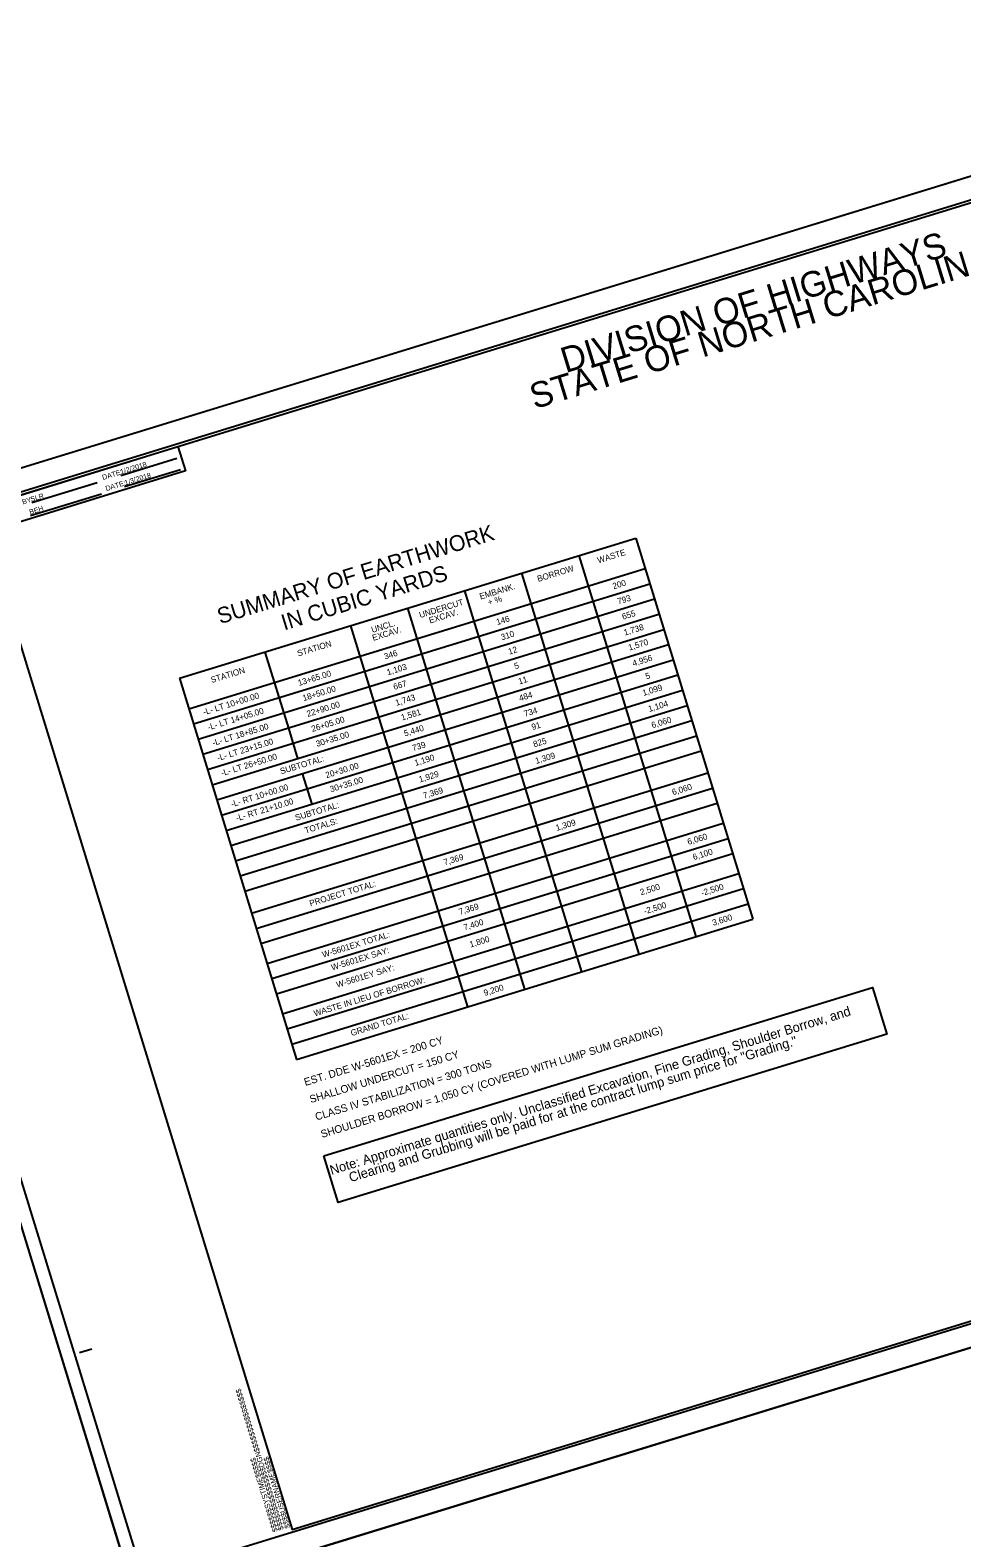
# Model space of a CAD drawing. Extents: x 2528815 to 2532488, y 739965 to 742287.
# Drawn here: x 2530077 to 2530992, y 740714 to 742195 of the extents above; entities that cross this region are included whole.
import ezdxf

# ---------------------------------------------------------------- set-up
doc = ezdxf.new("R2010")
doc.units = 0
for name, color, linetype in [('Prop Grid Mask', 7, 'Continuous'), ('Prop XSC Text', 7, 'Continuous'), ('Sheet Cutting Line CELL', 7, 'Continuous'), ('Sheet Data Field CELL', 7, 'Continuous'), ('Sheet Plot Border Inside CELL', 7, 'Continuous'), ('Sheet Plot Border Outside CELL', 7, 'Continuous'), ('Sheet Summary Combination CELL', 7, 'Continuous'), ('Sheet Summary Combination Grid CELL', 7, 'Continuous'), ('Sheet Summary Earthwork CELL', 7, 'Continuous')]:
    doc.layers.add(name, color=color, linetype=linetype)

msp = doc.modelspace()

# ---------------------------------------------------------------- linework, layer by layer
at = {"layer": 'Prop Grid Mask'}
msp.add_lwpolyline([(2530365.3, 741089.1), (2530904.3, 741254.7), (2530918.4, 741208.8), (2530379.4, 741043.2)], close=True, dxfattribs=at)
at = {"layer": 'Sheet Cutting Line CELL'}
for p, q in [((2531468.4, 742195.3), (2529858.7, 741700.6)), ((2529858.7, 741700.6), (2530181.8, 740649.1)), ((2531791.5, 741143.8), (2530181.8, 740649.1))]:
    msp.add_line(p, q, dxfattribs=at)
at = {"layer": 'Sheet Plot Border Inside CELL'}
msp.add_lwpolyline([(2531470.7, 742172.5), (2529877.7, 741682.9), (2530187.7, 740674.4), (2531780.6, 741163.9)], close=True, dxfattribs=at)
at = {"layer": 'Sheet Plot Border Outside CELL'}
msp.add_lwpolyline([(2531468.4, 742195.3), (2529858.7, 741700.6), (2530181.8, 740649.1), (2531791.5, 741143.8)], close=True, dxfattribs=at)
at = {"layer": 'Sheet Summary Combination CELL'}
for p, q in [((2530165.9, 741757.8), (2530220.9, 741774.7)), ((2530169.4, 741746.8), (2530224.4, 741763.7)), ((2530077.1, 741718.4), (2530146.8, 741739.8)), ((2530078.6, 741731.1), (2530142.7, 741750.8)), ((2530336.2, 741593), (2530336.2, 741593)), ((2530343.7, 741595.1), (2530343.7, 741595.1)), ((2530354.4, 741598.7), (2530354.4, 741598.7)), ((2530361.2, 741600.6), (2530361.2, 741600.6)), ((2530125.3, 740895.9), (2530137.3, 740899.6)), ((2530283.9, 740885.6), (2530283.9, 740885.6))]:
    msp.add_line(p, q, dxfattribs=at)
for points in [[(2531459.5, 742166.4), (2530025.7, 741725.7), (2530334.1, 740722), (2531767.9, 741162.7)], [(2530025.7, 741725.7), (2530221.9, 741786), (2530229.3, 741762.1), (2530033, 741701.8)]]:
    msp.add_lwpolyline(points, close=True, dxfattribs=at)
at = {"layer": 'Sheet Summary Combination Grid CELL'}
for p, q in [((2530223.4, 741558.4), (2530671.7, 741696.1)), ((2530671.7, 741696.1), (2530786.7, 741321.8)), ((2530615.7, 741678.9), (2530730.7, 741304.6)), ((2530615.7, 741678.9), (2530615.7, 741678.9)), ((2530232.6, 741528.5), (2530680.9, 741666.3)), ((2530237.2, 741513.6), (2530685.5, 741651.3)), ((2530559.6, 741661.7), (2530674.7, 741287.3)), ((2530241.8, 741498.6), (2530690.1, 741636.4)), ((2530503.6, 741644.5), (2530618.6, 741270.1)), ((2530246.4, 741483.7), (2530694.6, 741621.4)), ((2530447.5, 741627.2), (2530562.6, 741252.9)), ((2530251, 741468.8), (2530699.2, 741606.5)), ((2530391.5, 741610), (2530506.5, 741235.7)), ((2530255.6, 741453.8), (2530703.8, 741591.6)), ((2530255.6, 741453.8), (2530703.8, 741591.6)), ((2530260.2, 741438.9), (2530708.4, 741576.6)), ((2530307.5, 741584.2), (2530330.5, 741509.5)), ((2530264.8, 741424), (2530713, 741561.7)), ((2530223.4, 741558.4), (2530338.5, 741184)), ((2530269.3, 741409), (2530717.6, 741546.8)), ((2530269.3, 741409), (2530717.6, 741546.8)), ((2530273.9, 741394.1), (2530722.2, 741531.8)), ((2530278.5, 741379.1), (2530726.8, 741516.9)), ((2530283.1, 741364.2), (2530731.4, 741502)), ((2530330.5, 741509.5), (2530339.6, 741479.7)), ((2530287.7, 741349.3), (2530736, 741487)), ((2530294.3, 741327.7), (2530742.6, 741465.4)), ((2530344.2, 741464.7), (2530353.4, 741434.8)), ((2530298.9, 741312.7), (2530747.2, 741450.5)), ((2530303.5, 741297.8), (2530751.8, 741435.6)), ((2530309.5, 741278.3), (2530757.8, 741416)), ((2530314.1, 741263.3), (2530762.4, 741401.1)), ((2530318.7, 741248.4), (2530767, 741386.1)), ((2530324.7, 741228.8), (2530773, 741366.6)), ((2530329.3, 741213.9), (2530777.6, 741351.7)), ((2530333.9, 741199), (2530782.1, 741336.7)), ((2530333.9, 741199), (2530782.1, 741336.7)), ((2530338.5, 741184), (2530786.7, 741321.8)), ((2530338.5, 741184), (2530786.7, 741321.8))]:
    msp.add_line(p, q, dxfattribs=at)

# ---------------------------------------------------------------- texts
at = {"layer": 'Prop XSC Text'}
for s, p in [('Note: Approximate quantities only. Unclassified Excavation, Fine Grading, Shoulder Borrow, and ', (2530372.9, 741070.4)), ('    Clearing and Grubbing will be paid for at the contract lump sum price for "Grading."', (2530378.3, 741059.1))]:
    msp.add_text(s, height=9.375, rotation=17.0832, dxfattribs=at).set_placement(p)
at = {"layer": 'Sheet Data Field CELL'}
for s, p in [('1/2/2018', (2530166.1, 741758.7)), ('1/3/2018', (2530170.3, 741748)), ('SLR                   ', (2530077.9, 741731.7)), ('BEH                   ', (2530076.8, 741719.2))]:
    msp.add_text(s, height=5, rotation=17.0832, dxfattribs=at).set_placement(p)
at = {"layer": 'Sheet Summary Combination CELL'}
for s, height, rotation, p in [('DATE:', 5, 17.0832, (2530148.4, 741753.2)), ('DATE:', 5, 17.0832, (2530151.7, 741742.3)), ('COMPUTED BY:', 5, 17.0832, (2530030.1, 741717)), ('SUMMARY OF EARTHWORK', 15.625, 17.0952, (2530263.4, 741611.5)), ('WASTE', 6, 17.0832, (2530635.1, 741671.3)), ('IN CUBIC YARDS', 15.625, 17.0952, (2530326.3, 741605.3)), ('BORROW', 6, 17.0832, (2530576, 741653.1)), ('EMBANK.', 6, 17.0832, (2530519.3, 741635.7)), ('200', 6, 17.0832, (2530650, 741645.8)), ('UNDERCUT', 6, 17.0832, (2530460, 741617.5)), ('+ %', 6, 17.0832, (2530527.5, 741630)), ('793', 6, 17.0832, (2530654.7, 741630.9)), ('EXCAV.', 6, 17.0832, (2530469.6, 741612.2)), ('146', 6, 17.0832, (2530535.7, 741610.6)), ('655', 6, 17.0832, (2530659.3, 741615.9)), ('UNCL.', 6, 17.0832, (2530413, 741603)), ('EXCAV.', 6, 17.0832, (2530413.9, 741595.1)), ('310', 6, 17.0832, (2530540.3, 741595.7)), ('1,738', 6, 17.0832, (2530661, 741600.3)), ('STATION', 6, 17.0832, (2530340.2, 741579.8)), ('12', 6, 17.0832, (2530547.5, 741581.6)), ('1,570', 6, 17.0832, (2530665.5, 741585.6)), ('346', 6, 17.0832, (2530425.5, 741576.8)), ('4,956', 6, 17.0832, (2530669.5, 741570.1)), ('STATION', 6, 17.0832, (2530255.2, 741553.7)), ('13+65.00', 6, 17.0832, (2530340.9, 741550.8)), ('1,103', 6, 17.0832, (2530428.2, 741561.3)), ('5', 6, 17.0832, (2530553.4, 741567.2)), ('11', 6, 17.0832, (2530557.4, 741552.3)), ('5', 6, 17.0832, (2530682.3, 741557.2)), ('18+50.00', 6, 17.0832, (2530345.5, 741535.9)), ('667', 6, 17.0832, (2530434.6, 741546.9)), ('484', 6, 17.0832, (2530558.1, 741535.8)), ('1,099', 6, 17.0832, (2530679.3, 741541)), ('-L- LT 10+00.00', 6, 17.0832, (2530247.6, 741522.1)), ('22+90.00', 6, 17.0832, (2530349.5, 741520.4)), ('1,743', 6, 17.0832, (2530436.6, 741531.3)), ('734', 6, 17.0832, (2530562.9, 741520.5)), ('1,104', 6, 17.0832, (2530685, 741525.2)), ('-L- LT 14+05.00', 6, 17.0832, (2530252.1, 741507.2)), ('26+05.00', 6, 17.0832, (2530354.1, 741505.6)), ('1,581', 6, 17.0832, (2530442.2, 741516.9)), ('91', 6, 17.0832, (2530570.4, 741507.5)), ('6,060', 6, 17.0832, (2530688.2, 741509.3)), ('-L- LT 18+85.00', 6, 17.0832, (2530256.8, 741491.9)), ('30+35.00', 6, 17.0832, (2530358.6, 741490.9)), ('5,440', 6, 17.0832, (2530445, 741501.1)), ('-L- LT 23+15.00', 6, 17.0832, (2530261.4, 741477.1)), ('739', 6, 17.0832, (2530453.2, 741486.8)), ('825', 6, 17.0832, (2530572, 741490.5)), ('1,309', 6, 17.0832, (2530574, 741474.2)), ('-L- LT 26+50.00', 6, 17.0832, (2530265.2, 741462.2)), ('SUBTOTAL:', 6, 17.0832, (2530323.4, 741464)), ('20+30.00', 6, 17.0832, (2530368, 741460.2)), ('1,190', 6, 17.0832, (2530455.4, 741472.2)), ('30+35.00', 6, 17.0832, (2530372.3, 741446.3)), ('1,929', 6, 17.0832, (2530459.7, 741456)), ('-L- RT 10+00.00', 6, 17.0832, (2530275, 741431.7)), ('7,369', 6, 17.0832, (2530463.9, 741440)), ('6,060', 6, 17.0832, (2530708.4, 741443.5)), ('-L- RT 21+10.00', 6, 17.0832, (2530279.9, 741417.9)), ('SUBTOTAL:', 6, 17.0832, (2530338.2, 741418.4)), ('TOTALS:', 6, 17.0832, (2530347.5, 741405.8)), ('1,309', 6, 17.0832, (2530594.2, 741408.4)), ('6,060', 6, 17.0832, (2530723.5, 741394.6)), ('7,369', 6, 17.0832, (2530484, 741374.5)), ('6,100', 6, 17.0832, (2530728.8, 741379.7)), ('PROJECT TOTAL:', 6, 17.0832, (2530352.2, 741334.2)), ('2,500', 6, 17.0832, (2530677, 741345.2)), ('-2,500', 6, 17.0832, (2530737, 741344.5)), ('7,369', 6, 17.0832, (2530498.9, 741325.9)), ('-2,500', 6, 17.0832, (2530680.7, 741326.4)), ('3,600', 6, 17.0832, (2530747.9, 741315.2)), ('W-5601EX TOTAL:', 6, 17.0832, (2530364.7, 741283.8)), ('7,400', 6, 17.0832, (2530503.6, 741310.5)), ('W-5601EX SAY:', 6, 17.0832, (2530373.5, 741271.3)), ('1,800', 6, 17.0832, (2530509.5, 741293.8)), ('WASTE IN LIEU OF BORROW:', 6, 17.0832, (2530356.5, 741226.1)), ('W-5601EY SAY:', 6, 17.0832, (2530378.6, 741254.3)), ('9,200', 6, 17.0832, (2530523.4, 741246.2)), ('GRAND TOTAL:', 6, 17.0832, (2530392.7, 741206.8)), ('EST. DDE W-5601EX = 200 CY ', 7.5, 17.0832, (2530347.2, 741157.8)), ('SHOULDER BORROW = 1,050 CY (COVERED WITH LUMP SUM GRADING)', 7.5, 17.0832, (2530363.6, 741106.7)), ('SHALLOW UNDERCUT = 150 CY', 7.5, 17.0832, (2530352.6, 741140.9)), ('CLASS IV STABILIZATION = 300 TONS', 7.5, 17.0832, (2530358.1, 741123.8)), ('$$$$$$$$$$$$$$$$DGN$$$$$$$$$$$$$$$$', 5.25, 107.0832, (2530326.1, 740722.1)), ('$$$$$$SYSTIME$$$$$', 5.25, 107.0832, (2530320.3, 740720.3)), ('$$$$USERNAME$$$$', 5.25, 107.0832, (2530332.4, 740724))]:
    msp.add_text(s, height=height, rotation=rotation, dxfattribs=at).set_placement(p)
at = {"layer": 'Sheet Summary Earthwork CELL'}
for s, p in [('DIVISION OF HIGHWAYS', (2530602.8, 741858.2)), ('STATE OF NORTH CAROLINA', (2530572.3, 741822.7))]:
    msp.add_text(s, height=25, rotation=17.0832, dxfattribs=at).set_placement(p)

doc.saveas('drawing.dxf')
